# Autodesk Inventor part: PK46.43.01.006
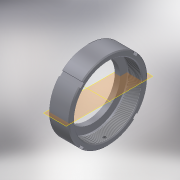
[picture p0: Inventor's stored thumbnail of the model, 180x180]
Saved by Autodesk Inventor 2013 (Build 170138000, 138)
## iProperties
Shininess: 64.0
Length Units: 11269
Angle Units: 11279
Time Units: 11290
Mass Units: 11283
Length Display Precision: 3
Angle Display Precision: 2
Compacted: True
Part Number: PK46.43.01.006
Document SubType Name: Modeling
Created: 2004-11
Material: Сталь высокопрочная низколегированная
Designer: ELarisa
Manufacturer: Standard
Standards Organization: Custom
Density: 7.84 g/cm^3
Density: 0.0
Volumn: 0.0
Area: 0.0
PropertySet Name: Model Information
Control State: 0
Master: False
Checked Out: False
Checked Out Date: 2008-10-09
Last Check In Date: 2008-10-09
Author: ELarisa
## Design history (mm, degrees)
revolve "Вращение1" stored, may be unused: angle "d8" = 90 deg
chamfer "Фаска1" distance "d9" = 2; stored, may be unused: second distance "d10" = 2, angle "d40" = 45 deg
feature "Резьба2" dims "d13" = 10, "d14" = 0
chamfer "Фаска2" distance "d15" = 2; stored, may be unused: second distance "d16" = 2, angle "d41" = 45 deg
node "РабОсь1"
node "РабПлоскость1"
sketch "Эскиз2"
  geometry: L1 (-24.211, 0)-(145.265, 0) reference; L2 (2, 87.5)-(2, -87.5) reference; 2 further points
  dimensions: "d18" = 0 distance from line of L1 point (37, 0); "d19" = 35 distance from line of L2 point (37, 0)
hole "Отверстие1" sketch "Эскиз2" at (37, 0), (121.054, 48.551) diameter "d20" = 6.647; stored, may be unused: countersink angle "d24" = 82 deg, drill point angle "d26" = 118 deg; dims "d21" = 15, "d22" = 11.2, "d23" = 2, "d25" = 20
sketch "Эскиз3"
  geometry: L1 (0, 0)-(0, -97.588); L2 (0, 0)-(-81.792, -81.792); L3 (-65.407, -65.407)-(-68.943, -61.872); L4 (-68.943, -61.872)-(-61.872, -54.801); L5 (-61.872, -54.801)-(-54.801, -61.872); L6 (-54.801, -61.872)-(-61.872, -68.943); L7 (-61.872, -68.943)-(-65.407, -65.407); C1 r 60 at (0, 0) reference; C2 r 85.5 at (0, 0) reference
  constraints: 14 end point, 3 perpendicular, 2 parallel, 2 point on line, 1 vertical
  dimensions: "d27" = 45 deg angle of L2 L1; "d29" = 82.5 distance from line of C1.centre L5; "d31" = 10 distance of L5.end L6.end; "d32" = 5 distance of L6.end L7.end; "d33" = 5 distance of L3.start L3.end; "d34" = 10 distance of L3.end L4.end
extrude "Выдавливание1" cut sketch "Эскиз3" stored distance "d35" = 10; taper "d36" = 0 deg
pattern_circular "Круговой массив1" dims angle "d39" = 360 deg
body "Solid1"
sketch "Эскиз1"
  geometry: L1 (0, 0)-(0, 87.5); L2 (0, 87.5)-(46, 87.5); L3 (46, 87.5)-(46, 0); L4 (46, 0)-(0, 0); L5 (0, 60)-(12, 60); L6 (12, 60)-(12, 75.5); L7 (12, 75.5)-(16, 75.5); L8 (16, 75.5)-(16.5, 75); L9 (16.5, 75)-(46, 75)
  constraints: 18 end point, 4 parallel, 3 perpendicular, 2 point on line, 1 vertical, 1 other
  dimensions: "d0" = 46 distance of L3.end L1.start; "d1" = 87.5 distance of L1.start L1.end; "d2" = 75.5 distance from line of L6.end L4; "d3" = 60 distance between parallel lines of L4 L5; "d4" = 75 distance between parallel lines of L4 L9; "d5" = 34 distance between parallel lines of L3 L6; "d6" = 4 distance of L6.end L7.end; "d7" = 135 deg angle of L9 L8
other parameters: "d17" = -87.5
